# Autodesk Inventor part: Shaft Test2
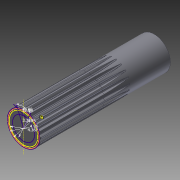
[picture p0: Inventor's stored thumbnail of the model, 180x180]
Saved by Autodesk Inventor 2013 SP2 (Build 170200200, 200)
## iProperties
Created: 2020-02
Part Number: Shaft Test2
Material: Steel
Document SubType Name: Modeling
Designer: DELL
Density: 1 g/cm^3
CustomPartVersion: 1
Author: DELL
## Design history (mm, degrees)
sketch "Sketch3"
  geometry: C1 r 2.5 at (0, 0); 1 further point
  constraints: 1 centre point, 1 coincident
  dimensions: "d16" = 5 diameter of C1
extrude "Extrusion1" new body sketch "Sketch3" distance "d18" = 20; taper "d19" = 0 deg
chamfer "Chamfer4" distance "d21" = 0.25; stored, may be unused: second distance "d22" = 2, angle "d23" = 45 deg
node "Involute Splining8"
sketch "Sketch4" dims "d21" = 0.25
  geometry: L1 (0, 0)-(1.12, 2.704); L2 (0, -3.533)-(0, 3.875) reference; L3 (0, 0)-(-1.12, 2.704); L4 (0.643, 1.552)-(-1.571, 2.469); C1 r 2.375 at (0, 0); C2 r 2.475 at (0, 0); C3 r 2.183 at (0, 0); C4 r 1.68 at (0, 0); 1 further point
  constraints: 6 end point, 4 centre point, 4 coincident, 1 perpendicular, 1 point on line, 1 tangent
  dimensions: "d46" = 4.75 diameter of C1; "d48" = 4.95 diameter of C2; "d49" = 4.367 diameter of C3; "d50" = 3.359 diameter of C4; "d52" = 22.5 deg angle of L1 L2; "d53" = 45 deg angle of L1 L3
sketch "Sketch5"
  geometry: L1 (0, -1.686)-(-0.333, -2.668); L2 (0, -1.686)-(0.336, -2.675); L3 (0, -3.753)-(0, 3.78) reference; 5 further points
  constraints: 4 end point, 2 other
  dimensions: "d54" = 1.6862 distance of L1.start point (0, 0); "d55" = 18.75 deg angle of L2 L3; "d56" = 18.75 deg angle of L3 L1 (= d55); "d57" = 37.5 deg angle of L2 L1 (derived)
body "Solid2"
feature "Shaft Groove"
